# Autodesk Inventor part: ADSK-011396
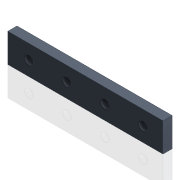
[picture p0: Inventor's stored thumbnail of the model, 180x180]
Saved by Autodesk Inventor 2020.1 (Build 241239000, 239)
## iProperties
Created: 2000-01
Part Number: ADSK-011396
Material: Nylatron
Document SubType Name: Modeling
Designer: glanglot
Density: 1.14 g/cm^3
Appearance: Métal - Plomb
Mass: 12.6059 g
Surface Area: 55.5262 cm^2
Volume: 11.0578 cm^3
Control State: 0
Checked Out: False
Master: False
Shininess: 0.0
Length Units: 11269
Angle Units: 11279
Time Units: 11290
Mass Units: 11283
Length Display Precision: 3
Angle Display Precision: 2
Compacted: True
Cutlength: 3 SI  (0.75 X 4.00)
Material Desc: SHEET,NYLATRON,0.250
Material_Number: A091494
Dimensions: 102x19x6 mm
Mass: 0,013 kg
Density: 0.0
Volumn: 0.0
Area: 0.0
PropertySet Name: Model Information
Author: glanglot
Revision Number: -
Title: ADSK-011396
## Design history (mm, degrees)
node "Solide1"
  node "Extrusion1" dims "d10" = 6, "d11" = 0
  node "Hole1" dims "d12" = 5.5, "d13" = 9.525, "d14" = 6.35, "d15" = 60 deg, "d16" = 19.05, "d17" = 118 deg, "d21" = 6
sketch "Sketch1"
  geometry: L1 (-102, 0)-(0, 0); L2 (0, 19)-(-102, 19); L3 (0, 0)-(0, 19); L4 (-102, 19)-(-102, 0); L5 (-88.094, 9.5)-(-13.094, 9.5); 6 further points
  constraints: 10 end point, 3 coincident, 2 horizontal, 2 point on line, 1 horizontal alignment, 1 midpoint, 1 perpendicular
  dimensions: "d0" = 19 distance between parallel lines of L2 L1; "d1" = 102 distance between parallel lines of L4 L3; "d18" = 25 distance of point (-63.094, 9.5) point (-88.094, 9.5) (= d20); "d19" = 25 distance of point (-13.094, 9.5) point (-38.094, 9.5) (= d20); "d20" = 25 distance of point (-63.094, 9.5) point (-38.094, 9.5)
node "Corps solides"
node "Corps surfaciques"
